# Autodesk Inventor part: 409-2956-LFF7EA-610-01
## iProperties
Created: 2011-01
Part Number: 409-2956-LFF7EA-610-01
Cost Center: 0 lbmass
Material: A36 STEEL PLATE
Document SubType Name: Sheet Metal
Designer: S. Boerckel
Authority: 0 in^3
Mass: 2841.15 g
Surface Area: 700.573 cm^2
Volume: 361.469 cm^3
Density: 7.86 g/cm^3
Flat Pattern Width: 7.62 cm
Flat Pattern Length: 38.1 cm
Flat Pattern Area: 290.322 cm^2
Sheet Metal Rule: 1/2"Thk
Description: TOP MOUNT PLATE
SaveDate: 2008-01-15
SaveTime: 10:24
FileName: Sheet Metal
Wide: =<Flat Pattern Width>cm
Length: =<Flat Pattern Length>cm
Thickness: 0.5000 in
SMR: =<Sheet Metal Rule> - <Material>
Author: S. Boerckel
Revision Number: 0
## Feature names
1. Hole1
2. Plate1
